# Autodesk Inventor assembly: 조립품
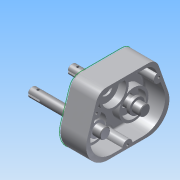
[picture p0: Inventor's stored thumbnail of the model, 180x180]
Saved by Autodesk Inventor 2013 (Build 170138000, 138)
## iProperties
Created: 2014-12
Part Number: 조립품
Document SubType Name: Assembly
Designer: Administrator
Author: Administrator
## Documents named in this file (4)
- C:\Users\Administrator\Desktop\441209V1007\조립품.iam
- C:\Users\Administrator\Desktop\441209V1007\본체.ipt
- C:\Users\Administrator\Desktop\441209V1007\오일시일-D-15.ipt
- C:\Users\Administrator\Desktop\441209V1007\서브축.ipt
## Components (2 placed, 1 different names)
1. KS B 2804 D D - 15 30 7:1
2. KS B 2804 D D - 15 30 7:2
